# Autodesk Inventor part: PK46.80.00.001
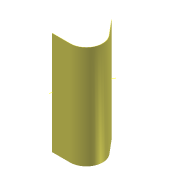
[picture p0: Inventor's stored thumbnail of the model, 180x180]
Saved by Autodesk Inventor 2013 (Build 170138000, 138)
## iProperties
Shininess: 64.0
Length Units: 11269
Angle Units: 11279
Time Units: 11290
Mass Units: 11283
Length Display Precision: 3
Angle Display Precision: 2
Compacted: True
Part Number: PK46.80.00.001
Document SubType Name: Sheet Metal
Created: 2005-01
Material: Steel, Mild
Designer: SAlex
Manufacturer: Standard
Standards Organization: Custom
Density: 7.86 g/cm^3
Flat Pattern Width: 185.556 cm
Flat Pattern Length: 258 cm
Flat Pattern Area: 47873.4 cm^2
Sheet Metal Rule: Default
Mass: 301208 g
Surface Area: 96512.8 cm^2
Volume: 38321.7 cm^3
Sheet Metal Width: 1855.558 mm
Sheet Metal Length: 2580.000 mm
Sheet Metal Area: 4787339.221 mm^2
Density: 0.0
Volumn: 0.0
Area: 0.0
PropertySet Name: Model Information
Control State: 0
Master: False
Checked Out: False
Checked Out Date: 2008-10-15
Last Check In Date: 2008-10-15
Author: SAlex
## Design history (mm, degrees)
node "Contour Flange1"
  sketch "Sketch1"
    geometry: L1 (0, -373.417)-(-450, -373.417); L2 (306.418, 283.698)-(-8.548, 659.06); A1 r 400 centre (0, 26.583) between (0, -373.417) and (306.418, 283.698)
    constraints: 4 end point, 2 point on circle, 2 tangent, 1 centre point, 1 horizontal, 1 other
    dimensions: "d0" = 800 diameter of A1; "d5" = 490 distance of L2.start L2.end; "d6" = 450 distance of L1.start L1.end; "d15" = 130 deg dimension on A1.centre L2.start L1.start
workplane "Work Plane1"
body "Solid1"
face "Plate1" dims "d8" = 2580, "d9" = 8 (= BendReliefWidth), "d11" = 16 (= MinimumRemnant), "d13" = 8 (= BendRadius), "d14" = 8, "Thickness" = 8
bend "Bend1" dims "d9" = 8 (= BendReliefWidth), "d10" = 4 (= BendReliefDepth), "d11" = 16 (= MinimumRemnant), "d12" = 8 (= BendRadius), "d13" = 8 (= BendRadius), "d14" = 8, "SeamGap" = 0.01, "Thickness" = 8
feature "Definition1"
other parameters: "BendRadius" = 8 (= Thickness), "BendReliefWidth" = 8 (= Thickness), "BendReliefDepth" = 4 (= 0.5 x Thickness), "CornerReliefSize" = 32 (= 4 x Thickness), "MinimumRemnant" = 16 (= 2 x Thickness), "TransitionRadius" = 8 (= BendRadius), "JacobiRadiusSize" = 8 (= Thickness), "GapSize" = 8 (= Thickness), "BendRadius" = 8, "BendReliefDepth" = 4, "BendReliefWidth" = 8, "CornerReliefSize" = 32, "GapSize" = 8, "JacobiRadiusSize" = 8, "MinimumRemnant" = 16, "Thickness" = 8, "TransitionRadius" = 8
